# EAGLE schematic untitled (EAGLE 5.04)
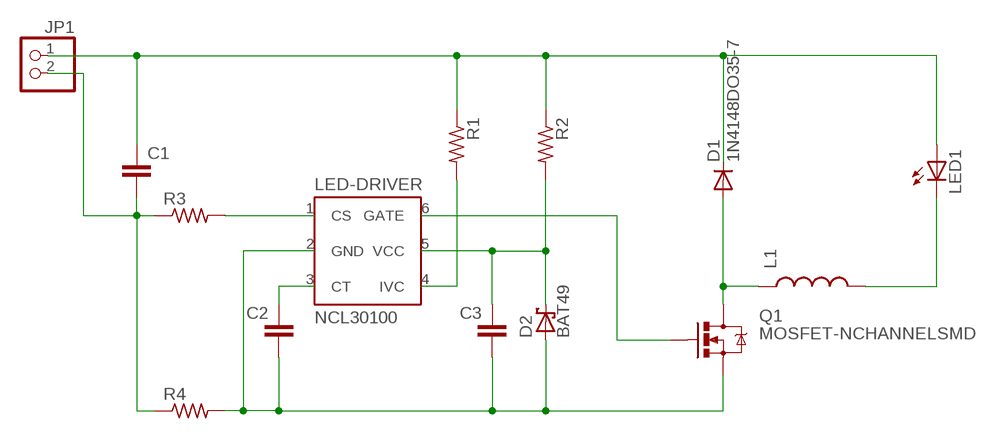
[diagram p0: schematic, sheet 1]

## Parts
C1  C-EUC1206  [C1206]
C2  C-EUC1206  [C1206]
C3  C-EUC1206  [C1206]
D1  1N4148DO35-7  [DO35-7]
D2  BAT49  [DO41-10]
JP1  PINHD-1X2  [1X02]
L1  INDUCTOR1206H*  [INDUCTOR-1206]
LED1  LEDLSU260  [LSU260]
LED-DRIVER  NCL30100  [SOT-23-6]
Q1  MOSFET-NCHANNELSMD  [SOT23-3]
R1  R-US_R1206  [R1206]
R2  R-US_R1206  [R1206]
R3  R-US_R1206  [R1206]
R4  R-US_R1206  [R1206]

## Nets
N$1: C1.1 D1.C JP1.1 LED1.A R1.1 R2.1
N$2: C1.2 JP1.2 R3.1 R4.1
N$3: LED-DRIVER.1(CS) R3.2
N$4: C2.1 LED-DRIVER.3(CT)
N$5: C2.2 C3.2 D2.A LED-DRIVER.2(GND) Q1.2(S) R4.2
N$6: D1.A L1.P$1 Q1.3(D)
N$8: C3.1 D2.C LED-DRIVER.5(VCC) R2.2
N$9: LED-DRIVER.4(IVC) R1.2
N$10: LED-DRIVER.6(GATE) Q1.1(G)
N$11: L1.P$2 LED1.K(C)

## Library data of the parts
C1-C3 = rcl:C-EU: CAPACITOR, European symbol
D1 = diode:1N4148: DIODE
D2 = diode:BAT49: DIODE
JP1 = pinhead:PINHD-1X2: PIN HEADER
L1 = SparkFun:INDUCTOR: Inductors
LED1 = led:LED: LED
LED-DRIVER = trl:NCL30100
Q1 = SparkFun:MOSFET-NCHANNEL
R1-R4 = rcl:R-US_: RESISTOR, American symbol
